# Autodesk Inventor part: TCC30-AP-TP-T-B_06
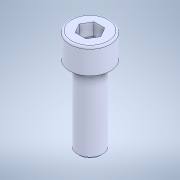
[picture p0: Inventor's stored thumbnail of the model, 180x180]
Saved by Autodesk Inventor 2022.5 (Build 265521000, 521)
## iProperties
Created: 2023-09
Part Number: TCC30-AP-TP-T-B_06
Material: 一般
Document SubType Name: Modeling
Designer: ImaoCorp
Density: 1 g/cm^3
Appearance: 既定
Author: ImaoCorp
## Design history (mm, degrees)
feature "TCC30-AP-TP-T-B_06"
node "ソリッド1"
